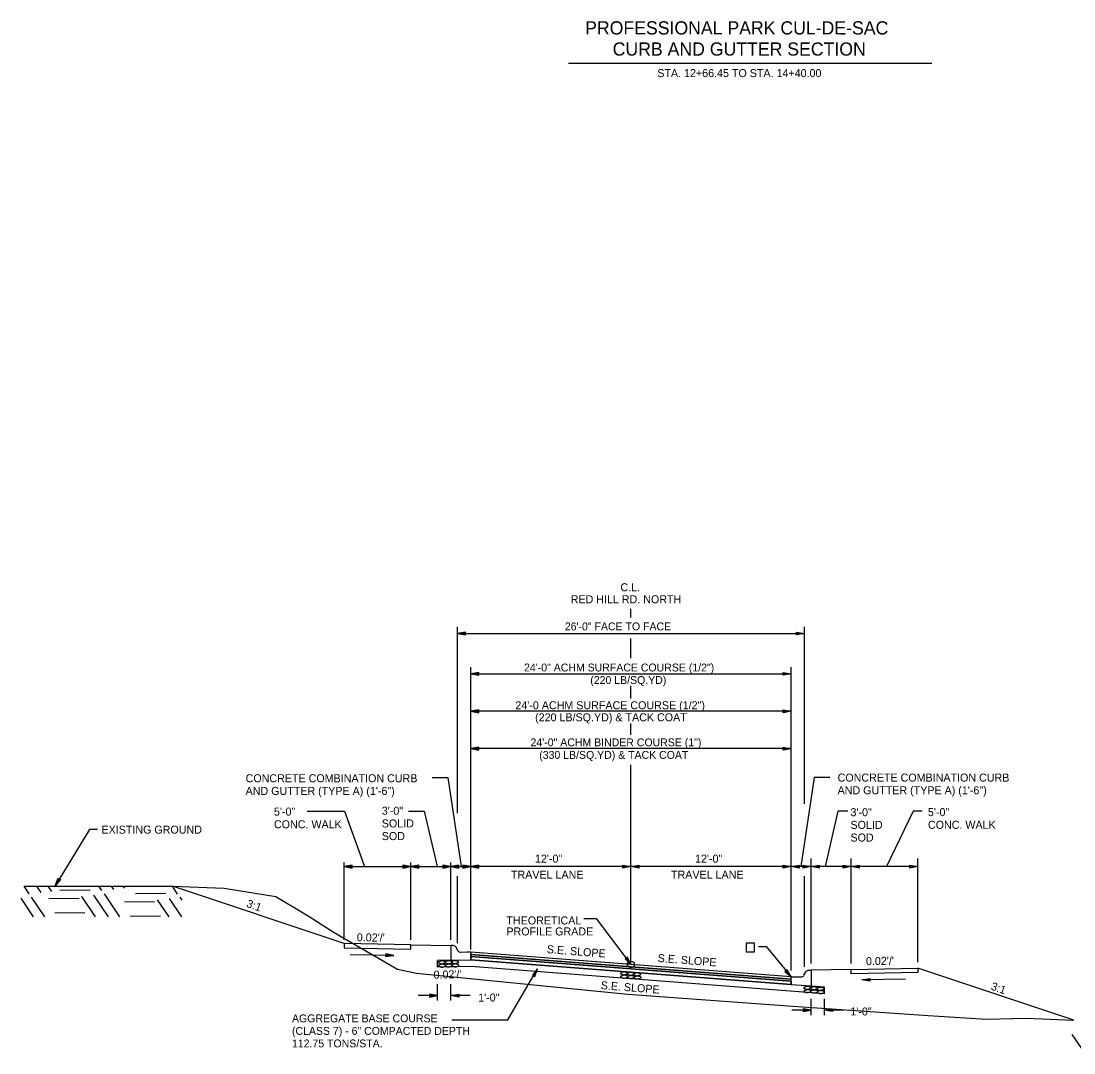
# Model space of a CAD drawing. Extents: x 1001270 to 1003428, y 1840152 to 1842912.
# Drawn here: x 1001294.8 to 1001373.7, y 1841333.5 to 1841410.8 of the extents above; entities that cross this region are included whole.
import ezdxf

# ---------------------------------------------------------------- set-up
doc = ezdxf.new("R2010")
doc.units = 0
for name, color, linetype in [('1', 7, 'Continuous'), ('19', 7, 'Continuous'), ('20', 7, 'Continuous'), ('8', 7, 'Continuous'), ('Level 1', 7, 'Continuous')]:
    doc.layers.add(name, color=color, linetype=linetype)

# ---------------------------------------------------------------- blocks, each defined once
blk = doc.blocks.new('TM')
at = {"layer": '8'}
for p, q in [((-120.309, 21.181), (-119.787, -20.829)), ((0, 0), (-120.309, 21.181)), ((-31.382, 2.945), (-120.176, 10.512)), ((-119.787, -20.829), (0, 0)), ((-119.911, -10.826), (-31.307, -3.057))]:
    blk.add_line(p, q, dxfattribs=at)
blk = doc.blocks.new('ROCKS')
at = {"layer": '1'}
blk.add_spline([(0.013, 0.06), (0.053, 0.053), (0.107, 0.033), (0.133, 0.013), (0.133, -0.007), (0.12, -0.033), (0.107, -0.04), (0.073, -0.053), (0.033, -0.067), (0.013, -0.067), (-0.02, -0.06), (-0.06, -0.053), (-0.087, -0.047), (-0.113, -0.02), (-0.113, -0.007), (-0.107, 0.02), (-0.087, 0.033), (-0.067, 0.047), (-0.033, 0.053), (-0.02, 0.06), (0.013, 0.06)], degree=3, dxfattribs=at)

msp = doc.modelspace()

# ---------------------------------------------------------------- linework, layer by layer
at = {"layer": '19'}
for p, q in [((1001335.847, 1841407.642), (1001363.07, 1841407.642)), ((1001340.522, 1841366.095), (1001340.522, 1841366.747)), ((1001327.522, 1841351.431), (1001327.522, 1841365.405)), ((1001353.522, 1841352.13), (1001353.522, 1841365.405)), ((1001328.122, 1841365.01), (1001327.522, 1841364.905)), ((1001327.522, 1841364.905), (1001353.522, 1841364.905)), ((1001327.522, 1841364.905), (1001328.122, 1841364.8)), ((1001328.122, 1841364.955), (1001327.682, 1841364.92)), ((1001327.682, 1841364.89), (1001328.122, 1841364.85)), ((1001328.122, 1841364.8), (1001328.122, 1841365.01)), ((1001340.522, 1841363.053), (1001340.522, 1841364.535)), ((1001352.922, 1841364.8), (1001352.922, 1841365.01)), ((1001352.922, 1841365.01), (1001353.522, 1841364.905)), ((1001352.922, 1841364.955), (1001353.362, 1841364.92)), ((1001353.522, 1841364.905), (1001352.922, 1841364.8)), ((1001353.362, 1841364.89), (1001352.922, 1841364.85)), ((1001328.522, 1841341.231), (1001328.522, 1841362.378)), ((1001352.522, 1841339.655), (1001352.522, 1841362.378)), ((1001329.122, 1841361.983), (1001328.522, 1841361.878)), ((1001328.522, 1841361.878), (1001329.122, 1841361.773)), ((1001328.522, 1841361.878), (1001352.522, 1841361.878)), ((1001329.122, 1841361.928), (1001328.682, 1841361.893)), ((1001328.682, 1841361.863), (1001329.122, 1841361.823)), ((1001329.122, 1841361.773), (1001329.122, 1841361.983)), ((1001351.922, 1841361.773), (1001351.922, 1841361.983)), ((1001351.922, 1841361.983), (1001352.522, 1841361.878)), ((1001351.922, 1841361.928), (1001352.362, 1841361.893)), ((1001352.522, 1841361.878), (1001351.922, 1841361.773)), ((1001352.362, 1841361.863), (1001351.922, 1841361.823)), ((1001340.522, 1841360.016), (1001340.522, 1841360.98)), ((1001329.122, 1841359.176), (1001328.522, 1841359.071)), ((1001328.522, 1841359.071), (1001329.122, 1841358.966)), ((1001352.522, 1841359.07), (1001328.522, 1841359.07)), ((1001329.122, 1841359.121), (1001328.682, 1841359.086)), ((1001328.682, 1841359.056), (1001329.122, 1841359.016)), ((1001329.122, 1841358.966), (1001329.122, 1841359.176)), ((1001351.922, 1841358.964), (1001351.922, 1841359.174)), ((1001351.922, 1841359.174), (1001352.522, 1841359.069)), ((1001351.922, 1841359.119), (1001352.362, 1841359.084)), ((1001352.522, 1841359.069), (1001351.922, 1841358.964)), ((1001352.362, 1841359.054), (1001351.922, 1841359.014)), ((1001340.522, 1841357.294), (1001340.522, 1841358.145)), ((1001329.122, 1841356.376), (1001328.522, 1841356.271)), ((1001328.522, 1841356.271), (1001329.122, 1841356.166)), ((1001352.522, 1841356.271), (1001328.522, 1841356.271)), ((1001329.122, 1841356.321), (1001328.682, 1841356.286)), ((1001328.682, 1841356.256), (1001329.122, 1841356.216)), ((1001329.122, 1841356.166), (1001329.122, 1841356.376)), ((1001351.922, 1841356.164), (1001351.922, 1841356.374)), ((1001351.922, 1841356.374), (1001352.522, 1841356.269)), ((1001351.922, 1841356.319), (1001352.362, 1841356.284)), ((1001352.522, 1841356.269), (1001351.922, 1841356.164)), ((1001352.362, 1841356.254), (1001351.922, 1841356.214)), ((1001340.522, 1841340.099), (1001340.522, 1841355.06)), ((1001325.612, 1841354.12), (1001326.791, 1841354.12)), ((1001326.791, 1841354.12), (1001327.779, 1841347.428)), ((1001354.262, 1841354.12), (1001353.248, 1841347.428)), ((1001355.441, 1841354.12), (1001354.262, 1841354.12)), ((1001316.252, 1841351.585), (1001319.045, 1841351.585)), ((1001319.045, 1841351.585), (1001320.539, 1841347.428)), ((1001323.848, 1841351.585), (1001325.027, 1841351.585)), ((1001325.027, 1841351.585), (1001325.983, 1841347.428)), ((1001356.026, 1841351.585), (1001355.07, 1841347.428)), ((1001356.77, 1841351.585), (1001356.026, 1841351.585)), ((1001361.676, 1841351.585), (1001359.669, 1841347.428)), ((1001362.353, 1841351.585), (1001361.676, 1841351.585)), ((1001354.022, 1841340.166), (1001354.022, 1841348.036)), ((1001357.022, 1841340.166), (1001357.022, 1841348.036)), ((1001362.022, 1841340.266), (1001362.022, 1841348.036)), ((1001319.022, 1841341.94), (1001319.022, 1841347.728)), ((1001319.622, 1841347.533), (1001319.022, 1841347.428)), ((1001319.022, 1841347.428), (1001328.522, 1841347.428)), ((1001319.022, 1841347.428), (1001319.622, 1841347.323)), ((1001319.622, 1841347.478), (1001319.182, 1841347.443)), ((1001319.182, 1841347.413), (1001319.622, 1841347.373)), ((1001319.622, 1841347.323), (1001319.622, 1841347.533)), ((1001323.422, 1841347.533), (1001323.422, 1841347.323)), ((1001324.022, 1841347.428), (1001323.422, 1841347.533)), ((1001323.862, 1841347.443), (1001323.422, 1841347.478)), ((1001323.422, 1841347.323), (1001324.022, 1841347.428)), ((1001323.422, 1841347.373), (1001323.862, 1841347.413)), ((1001324.022, 1841341.94), (1001324.022, 1841347.728)), ((1001324.622, 1841347.533), (1001324.022, 1841347.428)), ((1001324.022, 1841347.428), (1001324.622, 1841347.323)), ((1001324.622, 1841347.478), (1001324.182, 1841347.443)), ((1001324.182, 1841347.413), (1001324.622, 1841347.373)), ((1001324.622, 1841347.323), (1001324.622, 1841347.533)), ((1001326.422, 1841347.533), (1001326.422, 1841347.323)), ((1001327.022, 1841347.428), (1001326.422, 1841347.533)), ((1001326.862, 1841347.443), (1001326.422, 1841347.478)), ((1001326.422, 1841347.323), (1001327.022, 1841347.428)), ((1001326.422, 1841347.373), (1001326.862, 1841347.413)), ((1001327.022, 1841341.94), (1001327.022, 1841347.728)), ((1001327.622, 1841347.533), (1001327.022, 1841347.428)), ((1001327.022, 1841347.428), (1001327.622, 1841347.323)), ((1001327.622, 1841347.478), (1001327.182, 1841347.443)), ((1001327.182, 1841347.413), (1001327.622, 1841347.373)), ((1001327.622, 1841347.323), (1001327.622, 1841347.533)), ((1001327.922, 1841347.533), (1001327.922, 1841347.323)), ((1001328.522, 1841347.428), (1001327.922, 1841347.533)), ((1001328.362, 1841347.443), (1001327.922, 1841347.478)), ((1001327.922, 1841347.323), (1001328.522, 1841347.428)), ((1001327.922, 1841347.373), (1001328.362, 1841347.413)), ((1001329.122, 1841347.533), (1001328.522, 1841347.428)), ((1001328.522, 1841347.428), (1001329.122, 1841347.323)), ((1001340.522, 1841347.428), (1001328.522, 1841347.428)), ((1001329.122, 1841347.478), (1001328.682, 1841347.443)), ((1001328.682, 1841347.413), (1001329.122, 1841347.373)), ((1001329.122, 1841347.323), (1001329.122, 1841347.533)), ((1001339.922, 1841347.323), (1001339.922, 1841347.533)), ((1001339.922, 1841347.533), (1001340.522, 1841347.428)), ((1001339.922, 1841347.478), (1001340.362, 1841347.443)), ((1001340.522, 1841347.428), (1001339.922, 1841347.323)), ((1001340.362, 1841347.413), (1001339.922, 1841347.373)), ((1001340.522, 1841347.428), (1001341.122, 1841347.533)), ((1001352.522, 1841347.428), (1001340.522, 1841347.428)), ((1001341.122, 1841347.323), (1001340.522, 1841347.428)), ((1001340.682, 1841347.443), (1001341.122, 1841347.478)), ((1001341.122, 1841347.373), (1001340.682, 1841347.413)), ((1001341.122, 1841347.533), (1001341.122, 1841347.323)), ((1001351.922, 1841347.323), (1001351.922, 1841347.533)), ((1001351.922, 1841347.533), (1001352.522, 1841347.428)), ((1001351.922, 1841347.478), (1001352.362, 1841347.443)), ((1001352.522, 1841347.428), (1001351.922, 1841347.323)), ((1001352.362, 1841347.413), (1001351.922, 1841347.373)), ((1001352.522, 1841347.428), (1001353.122, 1841347.533)), ((1001362.022, 1841347.428), (1001352.522, 1841347.428)), ((1001353.122, 1841347.323), (1001352.522, 1841347.428)), ((1001352.682, 1841347.443), (1001353.122, 1841347.478)), ((1001353.122, 1841347.373), (1001352.682, 1841347.413)), ((1001353.122, 1841347.533), (1001353.122, 1841347.323)), ((1001353.422, 1841347.323), (1001353.422, 1841347.533)), ((1001353.422, 1841347.533), (1001354.022, 1841347.428)), ((1001353.422, 1841347.478), (1001353.862, 1841347.443)), ((1001354.022, 1841347.428), (1001353.422, 1841347.323)), ((1001353.862, 1841347.413), (1001353.422, 1841347.373)), ((1001354.022, 1841347.428), (1001354.622, 1841347.533)), ((1001354.622, 1841347.323), (1001354.022, 1841347.428)), ((1001354.182, 1841347.443), (1001354.622, 1841347.478)), ((1001354.622, 1841347.373), (1001354.182, 1841347.413)), ((1001354.622, 1841347.533), (1001354.622, 1841347.323)), ((1001356.422, 1841347.323), (1001356.422, 1841347.533)), ((1001356.422, 1841347.533), (1001357.022, 1841347.428)), ((1001356.422, 1841347.478), (1001356.862, 1841347.443)), ((1001357.022, 1841347.428), (1001356.422, 1841347.323)), ((1001356.862, 1841347.413), (1001356.422, 1841347.373)), ((1001357.022, 1841347.428), (1001357.622, 1841347.533)), ((1001357.622, 1841347.323), (1001357.022, 1841347.428)), ((1001357.182, 1841347.443), (1001357.622, 1841347.478)), ((1001357.622, 1841347.373), (1001357.182, 1841347.413)), ((1001357.622, 1841347.533), (1001357.622, 1841347.323)), ((1001361.422, 1841347.323), (1001361.422, 1841347.533)), ((1001361.422, 1841347.533), (1001362.022, 1841347.428)), ((1001361.422, 1841347.478), (1001361.862, 1841347.443)), ((1001362.022, 1841347.428), (1001361.422, 1841347.323)), ((1001361.862, 1841347.413), (1001361.422, 1841347.373)), ((1001297.339, 1841346.003), (1001297.563, 1841346.57)), ((1001297.74, 1841346.46), (1001297.339, 1841346.003)), ((1001297.413, 1841346.144), (1001297.606, 1841346.537)), ((1001297.699, 1841346.481), (1001297.436, 1841346.132)), ((1001297.563, 1841346.57), (1001297.74, 1841346.46)), ((1001327.522, 1841341.69), (1001327.522, 1841346.727)), ((1001353.522, 1841339.91), (1001353.522, 1841346.727)), ((1001295.402, 1841345.39), (1001295.021, 1841345.964)), ((1001296.297, 1841345.482), (1001295.965, 1841345.971)), ((1001297.092, 1841345.574), (1001296.83, 1841345.969)), ((1001299.968, 1841345.659), (1001297.708, 1841345.648)), ((1001300.856, 1841345.63), (1001300.63, 1841345.968)), ((1001301.751, 1841345.722), (1001301.585, 1841345.966)), ((1001302.546, 1841345.814), (1001302.44, 1841345.964)), ((1001306.531, 1841345.379), (1001306.14, 1841345.962)), ((1001319.022, 1841341.668), (1001306.14, 1841345.962)), ((1001295.729, 1841343.675), (1001294.793, 1841345.056)), ((1001296.584, 1841343.672), (1001295.588, 1841345.148)), ((1001299.138, 1841345.031), (1001296.868, 1841345.018)), ((1001300.384, 1841343.671), (1001299.352, 1841345.204)), ((1001301.339, 1841343.669), (1001300.247, 1841345.296)), ((1001302.194, 1841343.666), (1001301.042, 1841345.387)), ((1001304.803, 1841344.789), (1001302.543, 1841344.768)), ((1001305.643, 1841345.419), (1001303.383, 1841345.397)), ((1001305.894, 1841343.665), (1001305.027, 1841344.953)), ((1001306.849, 1841343.663), (1001305.922, 1841345.045)), ((1001306.871, 1841344.912), (1001306.717, 1841345.137)), ((1001299.58, 1841343.96), (1001297.32, 1841343.939)), ((1001305.256, 1841343.71), (1001302.985, 1841343.698)), ((1001324.021, 1841341.569), (1001319.022, 1841341.668)), ((1001319.022, 1841341.668), (1001319.022, 1841341.335)), ((1001319.022, 1841341.335), (1001324.021, 1841341.236)), ((1001324.021, 1841341.569), (1001327.022, 1841341.508)), ((1001324.021, 1841341.236), (1001324.021, 1841341.569)), ((1001324.021, 1841341.569), (1001324.021, 1841341.569)), ((1001327.188, 1841341.508), (1001327.022, 1841341.508)), ((1001327.022, 1841341.508), (1001327.022, 1841341.175)), ((1001327.022, 1841341.175), (1001327.022, 1841340.993)), ((1001327.022, 1841340.993), (1001327.022, 1841340.413)), ((1001327.551, 1841341.133), (1001327.405, 1841341.384)), ((1001328.238, 1841341.018), (1001327.772, 1841341.008)), ((1001328.522, 1841341.023), (1001328.238, 1841341.018)), ((1001328.238, 1841341.018), (1001328.238, 1841341.017)), ((1001328.238, 1841341.017), (1001328.238, 1841341.018)), ((1001327.022, 1841340.413), (1001326.022, 1841340.393)), ((1001326.022, 1841339.89), (1001326.022, 1841340.393)), ((1001327.022, 1841340.413), (1001328.522, 1841340.443)), ((1001328.522, 1841340.437), (1001352.522, 1841338.592)), ((1001340.249, 1841340.644), (1001340.082, 1841340.519)), ((1001340.082, 1841340.519), (1001340.522, 1841340.099)), ((1001340.121, 1841340.544), (1001340.414, 1841340.22)), ((1001340.436, 1841340.233), (1001340.209, 1841340.608)), ((1001340.522, 1841340.099), (1001340.249, 1841340.644)), ((1001328.522, 1841339.94), (1001326.022, 1841339.89)), ((1001331.298, 1841335.957), (1001333.521, 1841339.774)), ((1001333.521, 1841339.774), (1001333.129, 1841339.308)), ((1001333.129, 1841339.308), (1001333.31, 1841339.204)), ((1001333.43, 1841339.643), (1001333.176, 1841339.284)), ((1001333.267, 1841339.23), (1001333.455, 1841339.628)), ((1001333.31, 1841339.204), (1001333.521, 1841339.774)), ((1001352.224, 1841339.706), (1001352.062, 1841339.574)), ((1001352.062, 1841339.574), (1001352.522, 1841339.175)), ((1001352.1, 1841339.6), (1001352.409, 1841339.29)), ((1001352.43, 1841339.305), (1001352.185, 1841339.669)), ((1001352.522, 1841339.175), (1001352.224, 1841339.706)), ((1001353.493, 1841339.285), (1001353.639, 1841339.536)), ((1001353.855, 1841339.66), (1001354.022, 1841339.66)), ((1001354.022, 1841339.66), (1001354.022, 1841339.327)), ((1001354.022, 1841339.327), (1001354.022, 1841339.145)), ((1001357.03, 1841339.721), (1001354.031, 1841339.66)), ((1001357.03, 1841339.721), (1001362.029, 1841339.82)), ((1001357.03, 1841339.388), (1001357.03, 1841339.721)), ((1001357.03, 1841339.721), (1001357.03, 1841339.721)), ((1001362.029, 1841339.487), (1001357.03, 1841339.388)), ((1001362.029, 1841339.82), (1001362.029, 1841339.487)), ((1001373.733, 1841335.919), (1001362.029, 1841339.82)), ((1001326.022, 1841337.388), (1001326.022, 1841338.626)), ((1001327.022, 1841337.388), (1001327.022, 1841338.626)), ((1001352.522, 1841339.175), (1001352.806, 1841339.17)), ((1001352.522, 1841338.842), (1001352.522, 1841338.592)), ((1001352.522, 1841338.842), (1001352.522, 1841338.842)), ((1001352.522, 1841338.592), (1001352.522, 1841338.592)), ((1001352.522, 1841338.592), (1001352.522, 1841338.592)), ((1001354.022, 1841338.467), (1001352.522, 1841338.583)), ((1001352.806, 1841339.17), (1001352.806, 1841339.169)), ((1001352.806, 1841339.169), (1001352.806, 1841339.17)), ((1001352.806, 1841339.17), (1001353.272, 1841339.16)), ((1001354.022, 1841339.145), (1001354.022, 1841338.467)), ((1001326.022, 1841337.766), (1001324.573, 1841337.766)), ((1001325.422, 1841337.871), (1001325.422, 1841337.661)), ((1001326.022, 1841337.766), (1001325.422, 1841337.871)), ((1001325.862, 1841337.781), (1001325.422, 1841337.816)), ((1001325.422, 1841337.661), (1001326.022, 1841337.766)), ((1001325.422, 1841337.711), (1001325.862, 1841337.751)), ((1001327.022, 1841337.766), (1001327.622, 1841337.871)), ((1001327.622, 1841337.661), (1001327.022, 1841337.766)), ((1001328.471, 1841337.766), (1001327.022, 1841337.766)), ((1001327.182, 1841337.781), (1001327.622, 1841337.816)), ((1001327.622, 1841337.711), (1001327.182, 1841337.751)), ((1001327.622, 1841337.871), (1001327.622, 1841337.661)), ((1001355.022, 1841337.899), (1001355.022, 1841338.39)), ((1001354.022, 1841336.291), (1001354.022, 1841337.529)), ((1001355.022, 1841336.291), (1001355.022, 1841337.529)), ((1001354.022, 1841336.669), (1001352.573, 1841336.669)), ((1001354.022, 1841336.669), (1001352.573, 1841336.669)), ((1001353.422, 1841336.774), (1001353.422, 1841336.564)), ((1001354.022, 1841336.669), (1001353.422, 1841336.774)), ((1001353.422, 1841336.774), (1001353.422, 1841336.564)), ((1001354.022, 1841336.669), (1001353.422, 1841336.774)), ((1001353.862, 1841336.684), (1001353.422, 1841336.719)), ((1001353.862, 1841336.684), (1001353.422, 1841336.719)), ((1001353.422, 1841336.564), (1001354.022, 1841336.669)), ((1001353.422, 1841336.564), (1001354.022, 1841336.669)), ((1001353.422, 1841336.614), (1001353.862, 1841336.654)), ((1001353.422, 1841336.614), (1001353.862, 1841336.654)), ((1001355.022, 1841336.669), (1001355.622, 1841336.774)), ((1001355.022, 1841336.669), (1001355.622, 1841336.774)), ((1001355.622, 1841336.564), (1001355.022, 1841336.669)), ((1001356.471, 1841336.669), (1001355.022, 1841336.669)), ((1001355.622, 1841336.564), (1001355.022, 1841336.669)), ((1001356.471, 1841336.669), (1001355.022, 1841336.669)), ((1001355.182, 1841336.684), (1001355.622, 1841336.719)), ((1001355.182, 1841336.684), (1001355.622, 1841336.719)), ((1001355.622, 1841336.614), (1001355.182, 1841336.654)), ((1001355.622, 1841336.614), (1001355.182, 1841336.654)), ((1001355.622, 1841336.774), (1001355.622, 1841336.564)), ((1001355.622, 1841336.774), (1001355.622, 1841336.564)), ((1001327.084, 1841335.957), (1001331.298, 1841335.957)), ((1001374.547, 1841333.47), (1001373.611, 1841334.852))]:
    msp.add_line(p, q, dxfattribs=at)
for points in [[(1001300.522, 1841350.202), (1001299.922, 1841350.202), (1001297.339, 1841346.003)], [(1001295.019, 1841345.964), (1001306.14, 1841345.962)], [(1001306.14, 1841345.962), (1001310.028, 1841345.818), (1001313.884, 1841345.196), (1001316.309, 1841343.744), (1001318.272, 1841342.493), (1001323.018, 1841339.735), (1001324.433, 1841339.437), (1001340.279, 1841337.869), (1001352.649, 1841336.972), (1001362.815, 1841336.264), (1001367.165, 1841335.998), (1001370.151, 1841336.084), (1001373.733, 1841335.919)], [(1001336.994, 1841343.539), (1001337.901, 1841343.539), (1001340.522, 1841340.099)], [(1001349.154, 1841341.053), (1001349.795, 1841341.053), (1001349.795, 1841341.694), (1001349.154, 1841341.694), (1001349.154, 1841341.053)], [(1001349.795, 1841341.053), (1001349.795, 1841341.694), (1001349.154, 1841341.694), (1001349.154, 1841341.053), (1001349.795, 1841341.053)], [(1001328.522, 1841340.443), (1001328.522, 1841340.607), (1001328.522, 1841340.857), (1001328.522, 1841341.023)], [(1001352.522, 1841339.175), (1001340.522, 1841340.099), (1001328.522, 1841341.023)], [(1001352.522, 1841339.009), (1001340.522, 1841339.933), (1001328.522, 1841340.857)], [(1001350.079, 1841341.439), (1001350.649, 1841341.439), (1001352.522, 1841339.175)], [(1001352.522, 1841338.842), (1001340.522, 1841339.766), (1001328.522, 1841340.69)], [(1001352.522, 1841338.842), (1001328.522, 1841340.687), (1001328.522, 1841340.437)], [(1001352.522, 1841338.592), (1001340.522, 1841339.516), (1001328.522, 1841340.44)], [(1001355.022, 1841337.899), (1001340.522, 1841339.016), (1001328.522, 1841339.94)], [(1001352.522, 1841338.583), (1001352.522, 1841338.759), (1001352.522, 1841339.009), (1001352.522, 1841339.175)], [(1001355.022, 1841338.39), (1001354.022, 1841338.467)]]:
    msp.add_lwpolyline(points, dxfattribs=at)
for points in [[(1001328.522, 1841341.02), (1001328.522, 1841340.853), (1001352.522, 1841339.009), (1001352.522, 1841339.175)], [(1001328.522, 1841340.853), (1001328.522, 1841340.687), (1001352.522, 1841338.842), (1001352.522, 1841339.009)]]:
    msp.add_lwpolyline(points, close=True, dxfattribs=at)
msp.add_circle((1001340.522, 1841340.099), 0.25, dxfattribs=at)
for centre, start, end in [((1001327.188, 1841341.258), 30.1619, 90), ((1001327.767, 1841341.258), 210.16348, 271.14576), ((1001353.277, 1841339.41), 268.85424, 329.83652), ((1001353.855, 1841339.41), 90, 149.8381)]:
    msp.add_arc(centre, 0.25, start, end, dxfattribs=at)
at = {"layer": '20'}
for p, q in [((1001319.459, 1841340.849), (1001322.729, 1841340.784)), ((1001361.097, 1841339.006), (1001357.827, 1841338.941))]:
    msp.add_line(p, q, dxfattribs=at)

# ---------------------------------------------------------------- block references
at = {"layer": '19', "xscale": 0.0050063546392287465}
for p, yscale, rotation in [((1001322.73, 1841340.782), 0.005006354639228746, -1.1310771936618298), ((1001357.827, 1841338.938), -0.0050063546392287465, -178.8781640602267)]:
    msp.add_blockref('TM', p, dxfattribs=dict(at, yscale=yscale, rotation=rotation))
at = {"layer": 'Level 1', "xscale": 2.0116542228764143, "yscale": -2.0116542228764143, "rotation": -178.25539552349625}
for p in [(1001326.37, 1841340.267), (1001326.385, 1841340.019), (1001326.865, 1841340.277), (1001326.881, 1841340.029), (1001327.349, 1841340.282), (1001327.374, 1841340.037), (1001340.022, 1841339.442), (1001340.038, 1841339.195), (1001340.514, 1841339.412), (1001340.529, 1841339.164), (1001341.002, 1841339.37), (1001341.026, 1841339.126), (1001353.767, 1841338.354), (1001354.259, 1841338.323), (1001353.783, 1841338.106), (1001354.274, 1841338.076), (1001354.747, 1841338.281), (1001354.771, 1841338.037)]:
    msp.add_blockref('ROCKS', p, dxfattribs=at)

# ---------------------------------------------------------------- texts
at = {"layer": '19'}
for s, height, rotation, p in [('PROFESSIONAL PARK CUL-DE-SAC', 0.98999, 359.99538, (1001337.085, 1841409.785)), ('CURB AND GUTTER SECTION ', 0.98999, 359.99538, (1001339.15, 1841408.201)), ('STA. 12+66.45 TO STA. 14+40.00', 0.6, 359.99538, (1001342.494, 1841406.591)), ('CONCRETE COMBINATION CURB', 0.6, 360, (1001311.629, 1841353.752)), ('CONCRETE COMBINATION CURB', 0.6, 360, (1001356.013, 1841353.801)), ('AND GUTTER (TYPE A) (1\'-6")', 0.6, 360, (1001311.629, 1841352.802)), ('AND GUTTER (TYPE A) (1\'-6")', 0.6, 360, (1001356.013, 1841352.851)), ('5\'-0"', 0.6, 360, (1001313.755, 1841351.254)), ('3\'-0"', 0.6, 360, (1001321.838, 1841351.318)), ('3\'-0"', 0.6, 360, (1001356.98, 1841351.208)), ('5\'-0"', 0.6, 360, (1001362.786, 1841351.214)), ('CONC. WALK', 0.6, 360, (1001313.755, 1841350.304)), ('SOLID ', 0.6, 360, (1001321.838, 1841350.368)), ('SOLID ', 0.6, 360, (1001356.98, 1841350.258)), ('CONC. WALK', 0.6, 360, (1001362.786, 1841350.264)), ('SOD', 0.6, 360, (1001321.838, 1841349.418)), ('SOD', 0.6, 360, (1001356.98, 1841349.308)), ('12\'-0"', 0.6, 360, (1001333.324, 1841347.728)), ('12\'-0"', 0.6, 360, (1001345.324, 1841347.728)), ('TRAVEL LANE', 0.6, 360, (1001331.522, 1841346.528)), ('TRAVEL LANE', 0.6, 360, (1001343.522, 1841346.528)), ('3:1', 0.6, 340.49426, (1001311.647, 1841344.422)), ('THEORETICAL', 0.6, 360, (1001331.181, 1841343.098)), ("0.02'/'", 0.6, 358.85806, (1001319.961, 1841341.844)), ('PROFILE GRADE', 0.6, 360, (1001331.181, 1841342.273)), ('S.E. SLOPE', 0.6, 355.5967, (1001334.198, 1841340.954)), ('S.E. SLOPE', 0.6, 355.5967, (1001342.507, 1841340.291)), ("0.02'/'", 0.6, 1.14194, (1001358.146, 1841340.043)), ("0.02'/'", 0.6, 1.14194, (1001325.724, 1841339.032)), ('S.E. SLOPE', 0.6, 355.5967, (1001338.241, 1841338.251)), ('3:1', 0.6, 340.49426, (1001367.463, 1841338.227)), ('1\'-0"', 0.6, 360, (1001329.065, 1841337.323)), ('AGGREGATE BASE COURSE', 0.59001, 359.99538, (1001315.106, 1841335.766)), ('(CLASS 7) - 6" COMPACTED DEPTH', 0.59001, 359.99538, (1001315.105, 1841334.826)), ('112.75 TONS/STA.', 0.59001, 359.99538, (1001315.105, 1841333.886))]:
    msp.add_text(s, height=height, rotation=rotation, dxfattribs=at).set_placement(p)
for s, height, p in [('C.L.', 0.6, (1001339.734, 1841368.064)), ('RED HILL RD. NORTH', 0.6, (1001336.002, 1841367.164)), ('26\'-0" FACE TO FACE', 0.59001, (1001335.56, 1841365.135)), ('24\'-0" ACHM SURFACE COURSE (1/2")', 0.59001, (1001332.503, 1841362.056)), ('(220 LB/SQ.YD)', 0.59001, (1001337.47, 1841361.116)), ('24\'-0 ACHM SURFACE COURSE (1/2")', 0.6, (1001331.853, 1841359.221)), ('(220 LB/SQ.YD) & TACK COAT', 0.6, (1001333.334, 1841358.321)), ('24\'-0" ACHM BINDER COURSE (1")', 0.59001, (1001332.99, 1841356.447)), ('(330 LB/SQ.YD) & TACK COAT', 0.59001, (1001333.643, 1841355.507)), ('EXISTING GROUND', 0.6, (1001300.822, 1841349.902)), ('1\'-0"', 0.6, (1001356.97, 1841336.276))]:
    msp.add_text(s, height=height, dxfattribs=at).set_placement(p)

doc.saveas('drawing.dxf')
